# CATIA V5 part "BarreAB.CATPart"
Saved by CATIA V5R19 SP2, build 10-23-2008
Part number: BarreAB
Bounding box of the stored display mesh (mm): x -174.452 to -162.456, y -12 to 12, z -12 to 190
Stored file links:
  D:\France\IFMA\IAO\Projet\BarreAB.CATPart
  D:\France\IFMA\IAO\Projet\pruangdaja_CAO.CATProduct
  D:\France\IFMA\IAO\Projet\SqueletteAB.CATPart
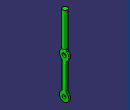
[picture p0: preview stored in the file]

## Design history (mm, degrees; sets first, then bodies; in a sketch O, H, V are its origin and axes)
Body1 (main body)
Body2
  Solid1: linked copy from another document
